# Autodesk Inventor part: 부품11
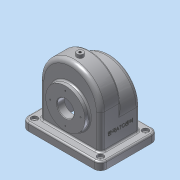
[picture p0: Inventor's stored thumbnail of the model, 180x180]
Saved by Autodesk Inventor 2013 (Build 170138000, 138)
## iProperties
Created: 2017-11
Part Number: 부품11
Material: 알루미늄 6061
Document SubType Name: Modeling
Designer: Administrator
Density: 2.71 g/cm^3
Mass: 1079.3 g
Surface Area: 1182.44 cm^2
Volume: 398.266 cm^3
Author: Administrator
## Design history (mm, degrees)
sketch "스케치1"
  geometry: L1 (58, 40)-(58, -40); L2 (58, -40)-(-58, -40); L3 (-58, -40)-(-58, 40); A1 r 58 centre (0, 40) between (0, 98) and (-58, 40); A2 r 58 centre (0, 40) between (58, 40) and (0, 98); 5 further points
  constraints: 6 end point, 4 point on circle, 2 centre point, 2 point on line, 2 tangent, 1 concentric, 1 horizontal, 1 horizontal alignment, 1 midpoint, 1 parallel, 1 vertical, 1 vertical alignment, 8 other
  dimensions: "d5" = 58 radius of A1; "d71" = 116 distance between parallel lines of L3 L1; "d73" = 80 distance from line of L2 A1.centre
extrude "돌출1" new body sketch "스케치1" stored distance "d7" = 38; taper "d8" = 0 deg
sketch "스케치3"
  geometry: L1 (-58, 17)-(-58, -40); L2 (-58, -40)-(58, -40); L3 (58, 17)-(58, -40); A1 r 58 centre (0, 17) between (58, 17) and (-58, 17); 2 further points
  constraints: 6 end point, 2 point on circle, 1 centre point, 1 horizontal alignment, 1 parallel, 1 perpendicular, 1 point on line, 1 tangent, 1 vertical, 1 vertical alignment
  dimensions: "d10" = 116 diameter of A1; "d11" = 57 distance from line of A1.centre L2
extrude "돌출2" join sketch "스케치3" distance "d12" = 38; taper "d13" = 0 deg
feature "쉘4" dims "d25" = 5
fillet "모깎기1" dims "d31" = 8
fillet "모깎기2" dims "d32" = 3
sketch "스케치8"
  geometry: L1 (-50, -40)-(50, -40) reference; C1 r 37.5 at (0, 25); 1 further point
  constraints: 1 centre point, 1 vertical alignment
  dimensions: "d39" = 75 diameter of C1; "d93" = 65 distance from line of C1.centre L1
extrude "돌출6" join sketch "스케치8" distance "d41" = 9; taper "d42" = 0 deg
sketch "스케치9"
  geometry: L1 (-50, -40)-(50, -40) reference; C1 r 31 at (0, 25); 1 further point
  constraints: 1 centre point, 1 vertical alignment
  dimensions: "d43" = 62 diameter of C1; "d94" = 65 distance from line of L1 C1.centre
extrude "돌출7" join sketch "스케치9" distance "d45" = 10; taper "d46" = 0 deg
sketch "스케치10"
  geometry: L1 (-50, -65)-(50, -65) reference; C1 r 16 at (0, 0); 1 further point
  constraints: 1 centre point, 1 vertical alignment
  dimensions: "d47" = 32 diameter of C1; "d95" = 65 distance from line of C1.centre L1
extrude "돌출8" cut sketch "스케치10" stored distance "d49" = 10; taper "d50" = 0 deg
sketch "스케치11"
  geometry: L1 (-50, -65)-(50, -65) reference; A1 r 29 centre (0, 0) between (0, 29) and (29, 0); 3 further points
  constraints: 4 point on circle, 3 vertical alignment, 2 horizontal alignment, 1 centre point
  dimensions: "d51" = 58 diameter of A1; "d96" = 65 distance from line of L1 A1.centre
hole "구멍1" sketch "스케치11" at (0, 29), (29, 0), (-29, 0), (0, -29) diameter "d53" = 2.459; stored, may be unused: countersink angle "d57" = 90 deg, drill point angle "d59" = 118 deg; dims "d54" = 6, "d55" = 4, "d56" = 2, "d58" = 8
sketch "스케치12"
  geometry: L1 (-50, -65)-(50, -65) reference; A1 r 26 centre (0, 0) between (0, 26) and (0, -26); 3 further points
  constraints: 4 point on circle, 3 vertical alignment, 2 horizontal alignment, 1 centre point
  dimensions: "d60" = 52 diameter of A1; "d97" = 65 distance from line of L1 A1.centre
hole "구멍2" sketch "스케치12" at (0, 26), (0, -26), (26, 0), (-26, 0) diameter "d63" = 2.459; stored, may be unused: countersink angle "d67" = 90 deg, drill point angle "d69" = 118 deg; dims "d64" = 6, "d65" = 4, "d66" = 2, "d68" = 8
sketch "스케치14"
  geometry: 1 further point
sketch "스케치15"
  geometry: L1 (-25, 17)-(125, 17); L2 (125, 17)-(125, -93); L3 (125, -93)-(-25, -93); L4 (-25, -93)-(-25, 17); L5 (108, -8)-(108, -68) reference; 4 further points
  constraints: 8 end point, 3 midpoint, 2 parallel, 1 horizontal, 1 horizontal alignment, 1 perpendicular, 1 vertical alignment
  dimensions: "d88" = 150 distance of L1.start L1.end; "d90" = 110 distance of L1.end L2.end
extrude "돌출10" join sketch "스케치15" distance "d91" = 15; taper "d92" = 0 deg
sketch "스케치16"
  geometry: L1 (22, -22)-(128, -22); L2 (128, -22)-(128, -88); L3 (128, -88)-(22, -88); L4 (22, -88)-(22, -22); L5 (150, 0)-(150, -110) reference; 4 further points
  constraints: 8 end point, 3 midpoint, 2 parallel, 1 horizontal, 1 horizontal alignment, 1 perpendicular, 1 vertical alignment
  dimensions: "d98" = 106 distance of L1.start L1.end; "d100" = 66 distance of L1.end L2.end
extrude "돌출11" cut sketch "스케치16" distance "d101" = 15; taper "d102" = 0 deg
node "작업 평면2"
sketch "스케치17"
  geometry: C1 r 6 at (-75, -36); 1 further point
  constraints: 1 centre point, 1 coincident
  dimensions: "d104" = 12 diameter of C1
extrude "돌출12" join sketch "스케치17" stored distance "d105" = 15; taper "d106" = 0 deg
hole "구멍4" diameter "d109" = 4.459; stored, may be unused: countersink angle "d113" = 90 deg, drill point angle "d115" = 118 deg; dims "d107" = 10, "d108" = 10, "d110" = 20, "d111" = 4, "d112" = 2, "d114" = 25
sketch "스케치18"
  geometry: 1 further point
fillet "모깎기6" dims "d116" = 12
fillet "모깎기7" dims "d117" = 3
sketch "스케치19"
  geometry: 1 further point
fillet "모깎기8" dims "d118" = 3
chamfer "모따기1" distance "d119" = 1; stored, may be unused: second distance "d120" = 2, angle "d121" = 45 deg
fillet "모깎기9" dims "d122" = 3
hole "구멍5" diameter "d125" = 5; stored, may be unused: countersink angle "d129" = 90 deg, drill point angle "d131" = 0 deg; dims "d123" = 10, "d124" = 10, "d126" = 20, "d127" = 12, "d128" = 5, "d130" = 15
hole "구멍6" diameter "d134" = 5; stored, may be unused: countersink angle "d138" = 90 deg, drill point angle "d140" = 0 deg; dims "d132" = 10, "d133" = 10, "d135" = 20, "d136" = 12, "d137" = 5, "d139" = 15
hole "구멍7" diameter "d143" = 5; stored, may be unused: countersink angle "d147" = 90 deg, drill point angle "d149" = 0 deg; dims "d141" = 10, "d142" = 10, "d144" = 20, "d145" = 12, "d146" = 5, "d148" = 15
hole "구멍8" diameter "d152" = 5; stored, may be unused: countersink angle "d156" = 90 deg, drill point angle "d158" = 0 deg; dims "d150" = 10, "d151" = 10, "d153" = 20, "d154" = 12, "d155" = 5, "d157" = 15
sketch "스케치20"
  geometry: L1 (-21.887, -13.398)-(27.887, -13.398); L2 (27.887, -13.398)-(27.887, -20.602); L3 (27.887, -20.602)-(-21.887, -20.602); L4 (-21.887, -20.602)-(-21.887, -13.398); L5 (-40, -57)-(46, -57) reference; L6 (-35, 23)-(-35, -39) reference; 4 further points
  constraints: 2 midpoint, 1 horizontal alignment, 1 vertical alignment, 2 other
  dimensions: "d159" = 40 distance from line of L5 point (3, -17); "d160" = 38 distance from line of L6 point (3, -17); "d161" = 49.77477 distance of L1.start L1.end; "d162" = 7.20489 distance of L1.end L2.end; "d163" = 24.88738 distance of point (3, -17) point (27.887, -17)
feature "엠보싱1" sketch "스케치20" dims "d5" = 58, "d71" = 116, "d73" = 80, "d164" = 0.5, "d165" = 0
node "솔리드1"
other parameters: "d103" = -144
